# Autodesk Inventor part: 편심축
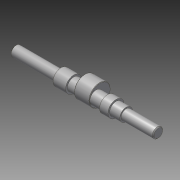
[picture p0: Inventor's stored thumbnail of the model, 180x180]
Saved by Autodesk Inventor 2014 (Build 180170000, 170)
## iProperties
Company: 한국ATC센터
Created: 2014-02
Part Number: 편심축
Document SubType Name: Modeling
Designer: KYOUNG IL JANG
Density: 7.86 g/cm^3
Mass: 251.263 g
Surface Area: 94.4893 cm^2
Volume: 31.9673 cm^3
Material: 강, 연강
Vendor: CBT Solutions
Appearance: 강철
Author: KYOUNG IL JANG
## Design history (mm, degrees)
sketch "스케치1"
  geometry: L1 (-84.5, 0)-(84.5, 0); L2 (-84.5, 0)-(-84.5, 6); L3 (-84.5, 6)-(-30.5, 6); L4 (-30.5, 6)-(-30.5, 9.5); L5 (-30.5, 9.5)-(-15.5, 9.5); L6 (-15.5, 9.5)-(-15.5, 7.5); L7 (-15.5, 7.5)-(46.5, 7.5); L8 (84.5, 6)-(84.5, 0); L9 (34.5, 7.5)-(34.5, 9.5); L10 (34.5, 9.5)-(24.5, 9.5); L11 (24.5, 9.5)-(24.5, 7.5); L12 (46.5, 7.5)-(46.5, 6); L13 (46.5, 6)-(84.5, 6); 2 further points
  constraints: 26 end point, 6 parallel, 6 perpendicular, 2 point on line, 1 coincident, 1 horizontal, 1 midpoint
  dimensions: "d1" = 12 diameter of L3 L1; "d2" = 15 diameter of L7 L1; "d4" = 15 distance of L4.end L5.end; "d5" = 19 diameter of L5 L1; "d24" = 10 distance of L9.end L10.end; "d25" = 19 diameter of L10 L1; "d27" = 40 distance between parallel lines of L11 L6; "d28" = 54 distance of L2.end L3.end; "d29" = 50 distance between parallel lines of L8 L9; "d41" = 38 distance between parallel lines of L8 L12; "d42" = 12 diameter of L13 L1
revolve "회전1" stored, may be unused: angle "d6" = 90 deg
node "작업 평면1"
sketch "스케치2"
  geometry: C1 r 7.5 at (0, 0) reference; C2 r 12.5 at (0, 4.5); 1 further point
  constraints: 1 centre point, 1 vertical alignment
  dimensions: "d8" = 4.5 distance of point (0, 0) C2.centre; "d9" = 25 diameter of C2
extrude "돌출1" join sketch "스케치2" distance "d10" = 18; taper "d11" = 0 deg
chamfer "모따기1" distance "d12" = 1; stored, may be unused: second distance "d13" = 2, angle "d14" = 45 deg
chamfer "모따기2" distance "d15" = 0.5; stored, may be unused: second distance "d16" = 2, angle "d17" = 45 deg
node "작업 평면2"
sketch "스케치3"
  geometry: L1 (4, -2)-(18, -2); L2 (18, 2)-(4, 2); L3 (27, 5)-(27, -5) reference; L4 (-136.5, -2.5)-(-127.5, -2.5); L5 (-127.5, 2.5)-(-136.5, 2.5); L6 (-142, -5)-(-142, 5) reference; A1 r 2 centre (18, 0) between (18, -2) and (18, 2); A2 r 2 centre (4, 0) between (4, 2) and (4, -2); A3 r 2.5 centre (-127.5, 0) between (-127.5, -2.5) and (-127.5, 2.5); A4 r 2.5 centre (-136.5, 0) between (-136.5, 2.5) and (-136.5, -2.5); 2 further points
  constraints: 8 end point, 8 point on circle, 8 tangent, 4 centre point, 2 horizontal, 2 horizontal alignment, 2 parallel, 1 midpoint
  dimensions: "d18" = 7 distance edge to line of A1 L3; "d19" = 4 distance between parallel lines of L2 L1; "d20" = 18 dimension on A1 A2; "d43" = 5 distance between parallel lines of L5 L4; "d44" = 14 dimension on A3 A4; "d45" = 3 distance edge to line of A4 L6
extrude "돌출2" cut sketch "스케치3" distance "d21" = 2.5; taper "d22" = 0 deg
revolve "회전2" stored, may be unused: angle "d26" = 90 deg
node "솔리드1"
other parameters: "d7" = 8.5
